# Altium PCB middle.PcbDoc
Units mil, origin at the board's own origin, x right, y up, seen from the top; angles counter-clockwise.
Board outline 3337.5 x 2235.24 mil, 2 copper layers (Top Layer, Bottom Layer); 23 components, 16 nets, 79 pads, 15 vias.
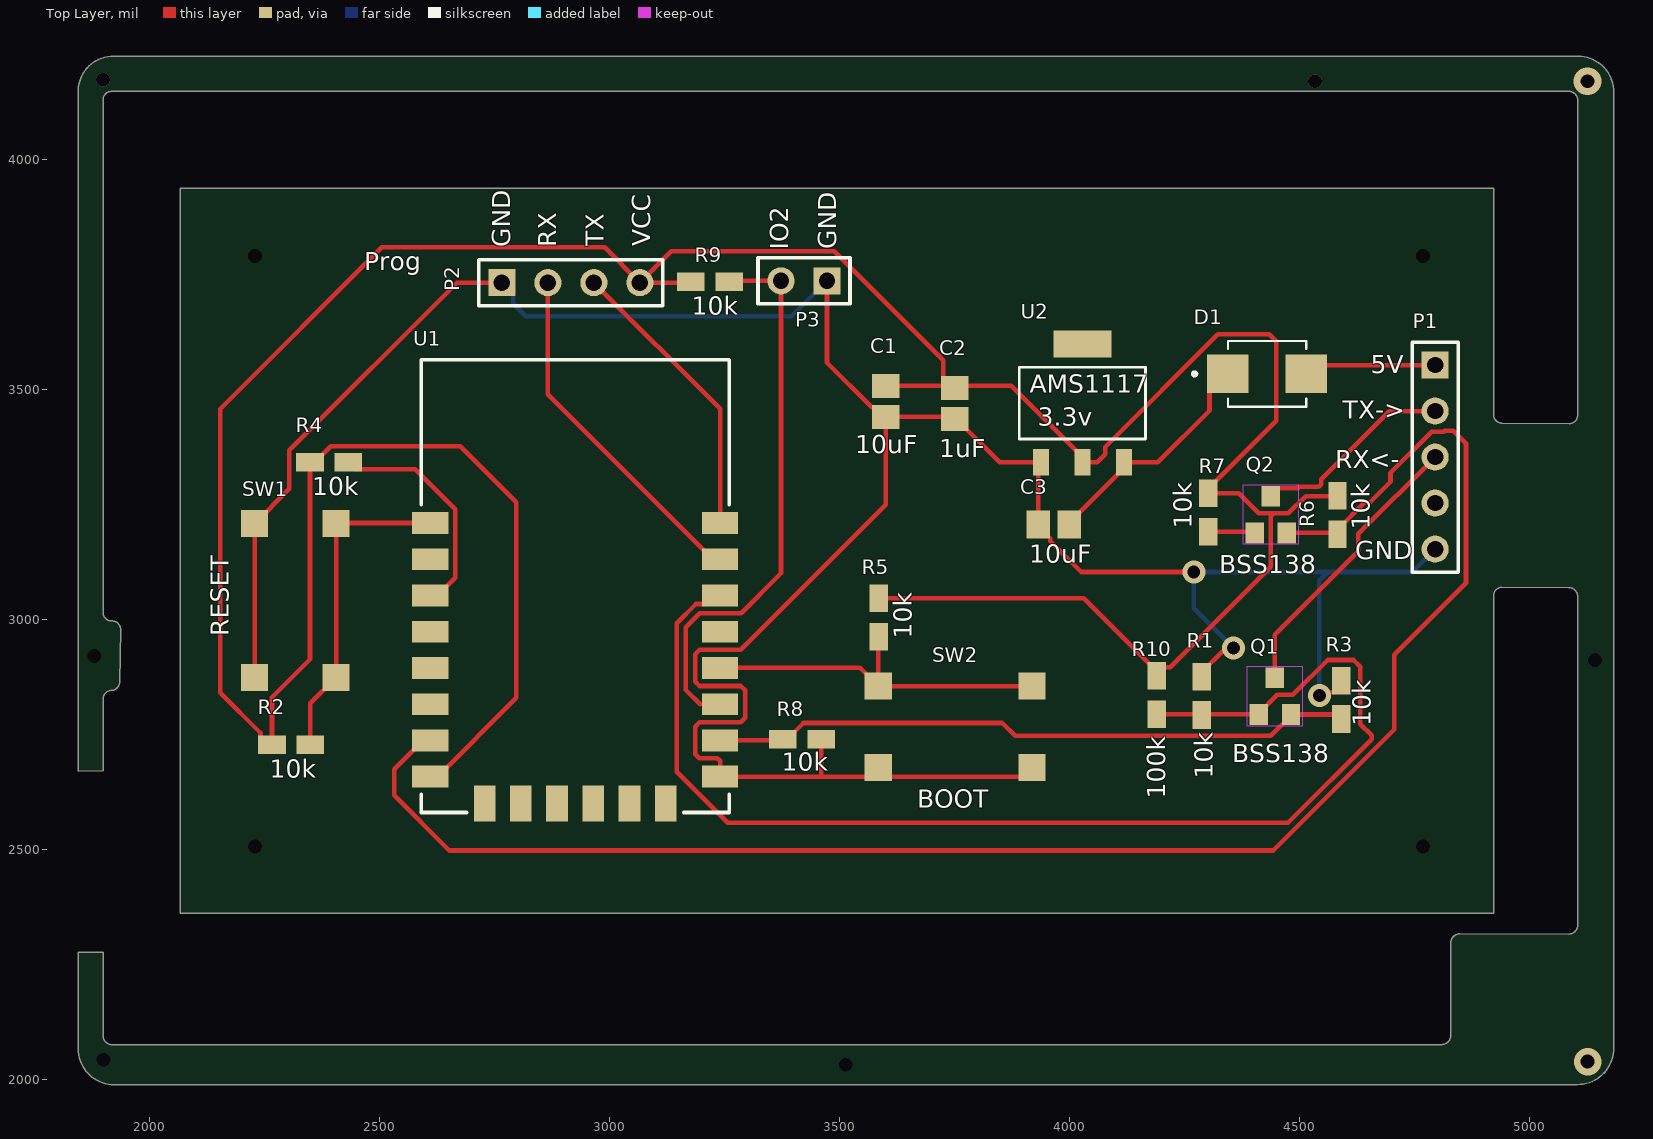
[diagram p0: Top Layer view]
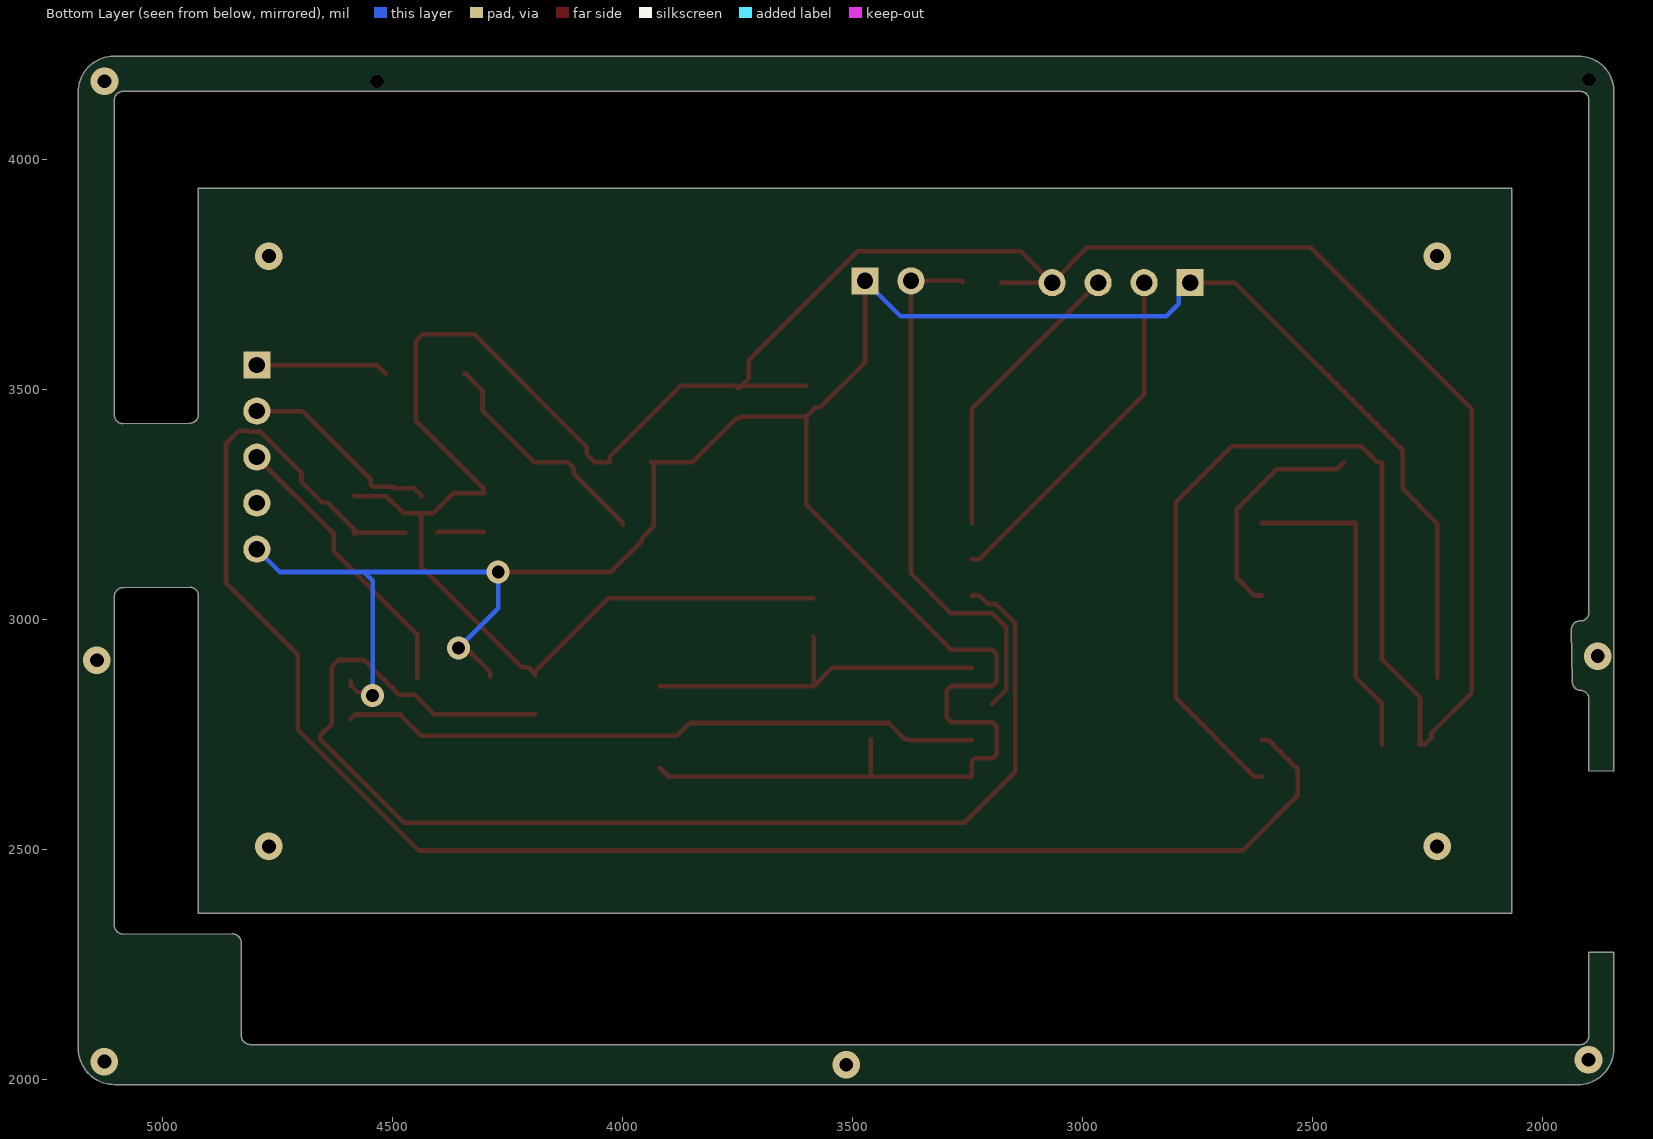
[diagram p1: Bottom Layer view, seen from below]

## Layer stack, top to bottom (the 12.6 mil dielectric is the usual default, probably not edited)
Top Solder: solder mask 0.4, Solder Resist, Dk 3.5
Top Layer: signal copper 1.4
Dielectric 1: dielectric 12.6, FR-4, Dk 4.8
Bottom Layer: signal copper 1.4
Bottom Solder: solder mask 0.4, Solder Resist, Dk 3.5

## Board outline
1845.04,2066.93 1845.04,2277.27 1899,2277 1899,2095 ccw(c1918.5,2095.5) 1919,2076 4808.31,2076.32 ccw(c4808.31,2096) 4828,2096 4828.31,2297.32 cw(c4848,2297.32) 4848,2317 5084.31,2316.32 ccw(c5084.31,2336) 5104,2336 5104,3051.18 ccw(c5085.5,3050.68) 5085,3069.18 4939.26,3070.18 ccw(c4939.76,3051.68) 4921.26,3051.18 4921.26,2362.2 2066.93,2362.2 2066.93,3937.01 4921.26,3937.01 4921.26,3444.88 ccw(c4939.76,3445.38) 4940.26,3426.88 5086,3425.88 ccw(c5085.5,3444.38) 5104,3444.88 5104,4130 ccw(c5085.18,4129.21) 5084.38,4148.03 1917,4148 ccw(c1917.5,4129.5) 1899,4129 1899,3015 ccw(c1917.5,3015.5) 1918,2997 cw(c1918.5,2978.5) 1937,2979 1935,2865 cw(c1916.5,2864.5) 1917,2846 ccw(c1917.5,2827.5) 1899,2827 1899,2671 1845.03,2670.83 1845,4150 cw(c1920.83,4148.58) 1922.24,4224.41 5105.31,4224.41 cw(c5105.03,4146.94) 5182.5,4146.65 5182.5,2068.9 cw(c5103.06,2068.61) 5103.35,1989.17 1923.23,1989.17 cw(c1923.01,2067.15)

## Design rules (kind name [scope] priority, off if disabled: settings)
Clearance [All] p1: gap=10 ignorepadtopadclearanceinfootprint=FALSE except(0: Arc-Hole Track-Hole SMDPad-Hole THPad-Hole Via-Hole Fill-Hole Poly-Hole Region-Hole Text-Hole)
PolygonConnect [All] p1: connectstyle=Relief reliefconductorwidth=10 reliefentries=4 polygonreliefangle="90 Angle" airgapwidth=10
RoutingVias [All] p1: holewidth=28 width=50 viastyle="Through Hole" minholewidth=28 minwidth=50 maxholewidth=28 maxwidth=50
SolderMaskExpansion [All] p1: expansion=4 istentingtop=FALSE
Width [All] p1: maxlimit=10 minlimit=10 preferedwidth=10
30 further rules are at their usual default settings.

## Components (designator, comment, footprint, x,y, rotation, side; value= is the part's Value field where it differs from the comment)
C1 "10uF" C0805 3600.39,3474.41 r270 top
C2 "1uF" C0805 3750,3469.49 r270 top
C3 "10uF" C0805 3965.55,3206.69 r180 top
D1 "Diode_M7" DO-214 4429,3534 r0 top
P1 "Header 5" HDR1X5 4794.29,3553.15 r270 top
P2 "Header 4" HDR1X4 2765.75,3732.28 r0 top
P3 "Header 2" HDR1X2 3472.44,3736.22 r180 top
Q1 "BSS138" SOT-23 4445.87,2833.66 r0 top value=IRLZ44NPBF
Q2 "BSS138" SOT-23 4437.01,3228.35 r0 top value=IRLZ44NPBF
R1 "10k" R0805W 4287.4,2834.65 r270 top
R2 "10k" R0805W 2308.07,2728.35 r180 top
R3 "10k" R0805W 4590.55,2825.79 r270 top
R4 "10k" R0805W 2390.75,3341.54 r180 top
R5 "10k" R0805W 3584.65,3003.94 r90 top
R6 "10k" R0805W 4582,3227 r90 top
R7 "10k" R0805W 4301.18,3232.28 r90 top
R8 "10k" R0805W 3418.31,2740.16 r180 top
R9 "10k" R0805W 3218.5,3734.25 r180 top
R10 "100k" R0805W 4188.98,2835.63 r90 top
SW1 "10-XX-6MD" BT6X6 2316.93,3041.34 r270 top
SW2 "10-XX-6MD" BT6X6 3750.98,2766.73 r0 top
U1 "ESP-12F" ESP-12F 2925.2,3072.83 r0 top
U2 "AMS1117" SOT-223 4027.56,3470.47 r0 top

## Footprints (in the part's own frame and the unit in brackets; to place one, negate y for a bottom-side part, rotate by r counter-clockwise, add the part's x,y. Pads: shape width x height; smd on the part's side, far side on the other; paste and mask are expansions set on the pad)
BT6X6 [mm]
  rect 1.5x1.5 smd: P(-4.25,2.25) P1(4.25,2.25) S(-4.25,-2.25) S1(4.25,-2.25)
C0805 [mil]
  rect 52x60 smd: 1(-33.46,0) 2(34,0)
DO-214 [mm]
  rect 2.28x2.12 smd: A(2.165,0) C(-2.165,0)
  silkscreen extent -4.1,-1.81 2.16,1.81
ESP-12F [mm]
  rect 2x1.2 smd: 1(-8,3.48) 2(-8,1.48) 3(-8,-0.52) 4(-8,-2.52) 5(-8,-4.52) 6(-8,-6.52) 7(-8,-8.52) 8(-8,-10.52) 15(8,-10.52) 16(8,-8.52) 17(8,-6.52) 18(8,-4.52) 19(8,-2.52) 20(8,-0.52) 21(8,1.48) 22(8,3.48)
  rect 1.2x2 smd: 9(-5,-12) 10(-3,-12) 11(-1,-12) 12(1,-12) 13(3,-12) 14(5,-12)
  silkscreen extent -8.5,-12.5 8.5,12.5
HDR1X2 [mm] "Connector; Header; 2 Position"
  rect 1.5x1.5 hole 0.9: 1(0,0)
  round 1.5 hole 0.9: 2(2.54,0)
  silkscreen extent -1.27,-1.27 3.81,1.27
HDR1X4 [mm] "Connector; Header; 4 Position"
  rect 1.5x1.5 hole 0.9: 1(0,0)
  round 1.5 hole 0.9: 2(2.54,0) 3(5.08,0) 4(7.62,0)
  silkscreen extent -1.27,-1.27 8.89,1.27
HDR1X5 [mm] "Connector; Header; 5 Position"
  rect 1.5x1.5 hole 0.9: 1(0,0)
  round 1.5 hole 0.9: 2(2.54,0) 3(5.08,0) 4(7.62,0) 5(10.16,0)
  silkscreen extent -1.27,-1.27 11.43,1.27
R0805W [mil]
  rect 60x40 smd: 1(-41.44,0) 2(42,0)
SOT-23 [mil]
  rect 40x45 smd: 1(-35,-40) 2(35,-40) 3(0,40)
  Top Layer keep-out region: -60,-65 -60,65 60,65 60,-65
SOT-223 [mil]
  rect 35x58 smd paste+0 mask+0: 1(-90.16,-128.5) 2(0,-128.5) 3(90.16,-128.5)
  rect 126x58 smd paste+0 mask+0: 4(0,128.5)
  silkscreen extent -137,-78 137,78, body extent 0,0 10,10, height 10

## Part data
C1 C2 C3: library part C-USC0805
P1: "Header, 5-Pin"
P2: "Header, 4-Pin"
P3: "Header, 2-Pin"
Q1 Q2: library part SI2302, Manufacturer_Part_Number=IRLZ44NPBF
R1 R2 R3 R4 R5 R6 R7 R8 R9 R10: library part R-US_R0805W
SW1 SW2: Package=BT4.5X4.5
U1: "WiFi Module", Package=Package

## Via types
v1: diameter 0/60 (per signal layer), hole 30, Top Layer to Bottom Layer, 8 vias
v2: diameter 50, hole 28, Top Layer to Bottom Layer, 3 vias
v3: diameter 30, hole 30, Top Layer to Bottom Layer, 2 vias
v4: diameter 60, hole 30, Top Layer to Bottom Layer, 2 vias

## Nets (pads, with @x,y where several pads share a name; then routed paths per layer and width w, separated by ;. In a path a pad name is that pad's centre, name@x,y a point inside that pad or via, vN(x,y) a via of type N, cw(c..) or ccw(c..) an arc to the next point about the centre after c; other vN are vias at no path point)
+5: D1.A P1.1 | length 288
  Top Layer w10: D1.A 4533.39,3553.15 P1.1
GND: C1.2 C2.2 C3.2 P1.5 P2.1 P3.1 R1.1 R3.1 R8.1 SW1.S SW1.S1 SW2.S SW2.S1 U1.15 U2.1 | length 6386.3
  Top Layer w10: SW1.S1 SW1.S 2303.75,3284.06 2303.75,3367.75 2668.28,3732.28 P2.1 ; R8.1 3459.74,2658.76 3459.65,2658.66 ; P3.1@3468.5,3732.28 P3.1 3472.44,3558.61 3569.65,3461.41 3579.39,3461.41 C1.2 ; SW2.S1 3898.82,2658.66 3459.65,2658.66 ; v2(4269.69,3103.35) 4025.15,3103.35 3958.02,3170.48 3958.02,3176.23 3931.55,3202.69 C3.2 3931.55,3336.12 U2.1 3847.52,3341.97 3754,3435.49 C2.2 3745.08,3440.41 C1.2 ; R1.1 4287.4,2886.08 4331.66,2930.34 4348.65,2930.34 v2(4356.3,2937.99) ; v2(4542.76,2835.06) 4549.92,2842.22 4575.55,2842.22 4590.55,2857.22 R3.1 ; 3459.65,2658.66 U1.15 3240.16,2692.92 3234.3,2698.78 3194.57,2698.78 3185.79,2707.57 3185.79,2767.24 3195.32,2776.77 3284.99,2776.77 3294.53,2786.31 3294.53,2845.98 3284.99,2855.51 3195.32,2855.51 3185.79,2865.05 3185.79,2924.72 3195.32,2934.25 3284.99,2934.25 3600.39,3249.65 C1.2
  Bottom Layer w10: P2.1 2790.28,3707.76 2790.28,3686.72 2818,3659 3395.22,3659 P3.1 ; v2(4356.3,2937.99) 4269.69,3024.61 v2(4269.69,3103.35) 4562.01,3103.35 ; v2(4542.76,2835.06) 4542.76,3084.1 4562.01,3103.35 ; P1.5 4744.49,3103.35 4562.01,3103.35
GPIO2: P3.2 R9.1 U1.17 | length 1184.6
  Top Layer w10: 3196.85,2815.94 3165.79,2847.01 3165.79,2983.46 3196.07,3013.74 3285.74,3013.74 3372.44,3100.44 P3.2 3261.91,3736.22 R9.1
GPIO5: Q1.1 R1.2 R10.1 U1.20 | length 2740.3
  Top Layer w10: U1.20 3224.41,3052.36 3205.79,3033.74 3187.79,3033.74 3145.79,2991.74 3145.79,2668.83 3256.54,2558.07 4474.41,2558.07 4656.29,2739.95 4656.29,2748.24 4631.89,2772.64 4631.89,2897.1 4616.76,2912.22 4561.14,2912.22 4485.07,2836.16 4450.87,2836.16 4410.33,2795.63 4410.33,2794.19 4287.4,2794.19 R10.1
GPIO13: Q2.2 R6.1 U1.7 | length 3692.4
  Top Layer w10: U1.7 2594.49,2737.4 2531.5,2674.41 2531.5,2618.11 2651.57,2498.03 4442.65,2498.03 4705.71,2761.09 4705.71,2923.23 4861.22,3078.74 4861.22,3382.87 4833.66,3410.43 4814.55,3410.43 4812.74,3408.62 4786.79,3408.62 4697.16,3318.99 4697.16,3299.58 4652.65,3255.07 4641.51,3255.07 4582,3195.56 R6.1 4579.22,3188.35 Q2.2
GPIO15: Q1.2 R3.2 R8.2 U1.16 | length 1402
  Top Layer w10: U1.16 3373.55,2737.4 R8.2 3386.31,2740.16 3421.31,2775.16 3853.71,2775.16 3881.22,2747.65 4437.35,2747.65 4480.87,2791.16 Q1.2 4580.68,2793.66 R3.2
NetC3_1: C3.1 D1.C U2.3 | length 515.2
  Top Layer w10: C3.1 3999.02,3210.69 4105.22,3316.89 4105.22,3329.47 U2.3 4191.58,3341.97 4303.88,3454.28 4303.88,3497.27 4340.61,3534 D1.C
NetQ2_1: Q2.1 R7.1 | length 101.9
  Top Layer w10: R7.1 4399.51,3190.85 Q2.1
NetR2_1: R2.1 SW1.P SW1.P1 U1.1 | length 708.7
  Top Layer w10: R2.1 2349.51,2818.01 SW1.P1 SW1.P 2406.69,3209.84 U1.1
NetR4_1: R4.1 U1.3 | length 493.7
  Top Layer w10: R4.1 2447.18,3326.54 2577.75,3326.54 2664.61,3239.68 2664.61,3090.98 2625.98,3052.36 U1.3
NetR5_1: R5.1 SW2.P SW2.P1 U1.18 | length 802.1
  Top Layer w10: U1.18 3544.09,2894.88 SW2.P ; R5.1 3583.66,2961.52 SW2.P ; SW2.P1 SW2.P
P_RX: P1.3 Q1.3 | length 623.8
  Top Layer w10: Q1.3 4445.87,2967.07 4627.52,3148.73 4627.52,3186.38 P1.3
P_TX: P1.2 Q2.3 | length 441.7
  Top Layer w10: Q2.3 4437.01,3270.85 4452.01,3285.85 4495.39,3285.85 4497.92,3288.38 4541.14,3288.38 4547,3294.24 4547,3305.21 4694.94,3453.15 P1.2
RX: P2.2 U1.21 | length 765.5
  Top Layer w10: P2.2 2865.75,3489.76 3224.41,3131.1 U1.21
TX: P2.3 U1.22 | length 636.1
  Top Layer w10: P2.3 3240.16,3457.87 U1.22
VCC: C1.1 C2.1 P2.4 R2.2 R4.2 R5.2 R6.2 R7.2 R9.2 R10.2 U1.8 U2.2 | length 7575.3
  Top Layer w10: U1.8 2625.98,2658.66 2797.24,2829.92 2797.24,3254.92 2675.63,3376.54 2393.75,3376.54 2358.75,3341.54 R4.2 2348.75,2914.14 2266.07,2831.47 R2.2 2256.07,2728.35 2241.07,2743.35 2241.07,2753.35 2153.54,2840.87 2153.54,3457.68 2504.72,3808.85 2989.18,3808.85 P2.4 ; R9.2 3174.54,3732.28 P2.4 ; R5.2 4030.67,3045.94 R10.2@4188.98,2887.63 ; C1.1 C2.1@3741.08,3507.87 ; C2.1 3746,3502.95 C2.1@3741.08,3507.87 ; C2.1@3750,3507.87 3873.16,3507.87 4027.56,3353.47 U2.2 4060.06,3341.97 4077.03,3358.94 4077.03,3375.09 4322.02,3620.08 4434.1,3620.08 4449.06,3605.13 4449.06,3432.16 4301.18,3284.28 R7.2 4367.36,3274.28 4410.79,3230.85 4443.09,3230.85 ; R10.2 4188.98,2881.27 4192.16,2884.45 4203.98,2896.27 4218.12,2896.27 4437.01,3115.16 4437.01,3224.76 4443.09,3230.85 ; R6.2 4581.38,3268.38 4512.92,3268.38 4475.39,3230.85 4443.09,3230.85 ; P2.4 3134.21,3800.75 3488.18,3800.75 3725,3563.93 3725,3523.95 C2.1@3741.08,3507.87
pads on no net: P1.4 U1.2 U1.4 U1.5 U1.6 U1.9 U1.10 U1.11 U1.12 U1.13 U1.14 U1.19 U2.4
copper on no net:
  other v1: 3513.22,2032.57 1899.93,2043.23 2229,2507 4768,2507 5141.86,2911.55 1879.88,2920.68 2229,3790 4768,3790
  other v3: 4532.86,4170.23 1898.82,4173.18
  other v4: 5125.64,2039.17 5125.41,4170.25

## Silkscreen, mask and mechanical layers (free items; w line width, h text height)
Top Overlay:
  text "TX" at 2987.49,3811.35 h40 r90
  text "VCC" at 3088.49,3811.35 h40 r90
  text "GND" at 2784.49,3809.35 h40 r90
  text "RX" at 2884.49,3809.35 h40 r90
  text "GND" at 3492.49,3804.35 h40 r90
  text "IO2" at 3388.49,3803.35 h40 r90
  text "Prog" at 2466.63,3759.49 h40
  text "10k" at 3179,3663 h40
  text "5V" at 4654,3535 h40
  text "AMS1117" at 3913.42,3492.92 h40
  text "TX->" at 4593,3436 h40
  text "3.3v" at 3930.15,3421.15 h40
  text "10uF" at 3534,3362 h40
  text "1uF" at 3716,3353 h40
  text "RX<-" at 4577,3329 h40
  text "10k" at 2354,3270 h40
  text "10k" at 4265,3197 h40 r90
  text "10k" at 4652,3195 h40 r90
  text "GND" at 4621,3131 h40
  text "10uF" at 3912,3123 h40
  text "BSS138" at 4325.15,3101.15 h40
  text "RESET" at 2172,2964 h40 r90
  text "10k" at 3657,2958 h40 r90
  text "10k" at 4654,2768 h40 r90
  text "BSS138" at 4353.63,2690.16 h40
  text "10k" at 3374,2671 h40
  text "10k" at 2261,2656 h40
  text "10k" at 4311,2654 h40 r90
  text "100k" at 4208,2610 h40 r90
  text "BOOT" at 3669,2591 h40
Mechanical 15:
  lines w1: 1844.35,2277.32 1899.16,2276.96 ; 1845.2,2670.92 1898.81,2671.13 ; 1918,2997 cw(c1918.5,2978.5) 1937,2979 ; 1918,2997 cw(c1918.5,2978.5) 1937,2979 ; 1918,2997 cw(c1917.5,3015.5) 1899,3015 1899,4129 cw(c1917.5,4129.5) 1917,4148 5084.38,4148.03 cw(c5085.18,4129.21) 5104,4130 5104,3444.88 cw(c5085.5,3444.38) 5086,3425.88 4940.26,3426.88 cw(c4939.76,3445.38) 4921.26,3444.88 4921.26,3937.01 2066.93,3937.01 2066.93,2362.2 4921.26,2362.2 4921.26,3051.18 cw(c4939.76,3051.68) 4939.26,3070.18 5085,3069.18 cw(c5085.5,3050.68) 5104,3051.18 5104,2336 cw(c5084.31,2336) 5084.31,2316.32 4848,2317 ccw(c4848,2297.32) 4828.31,2297.32 4828,2096 cw(c4808.31,2096) 4808.31,2076.32 1919,2076 cw(c1918.5,2095.5) 1899,2095 1899,2277 1845.04,2277.27 1845.04,2066.93 ccw(c1923.01,2067.15) 1923.23,1989.17 5103.35,1989.17 ccw(c5103.06,2068.61) 5182.5,2068.9 5182.5,4146.65 ccw(c5105.03,4146.94) 5105.31,4224.41 1922.24,4224.41 ccw(c1920.83,4148.58) 1845,4150 1845.03,2670.83 1899,2671 1899,2827 cw(c1917.5,2827.5) 1917,2846 ccw(c1916.5,2864.5) 1935,2865 1937,2979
